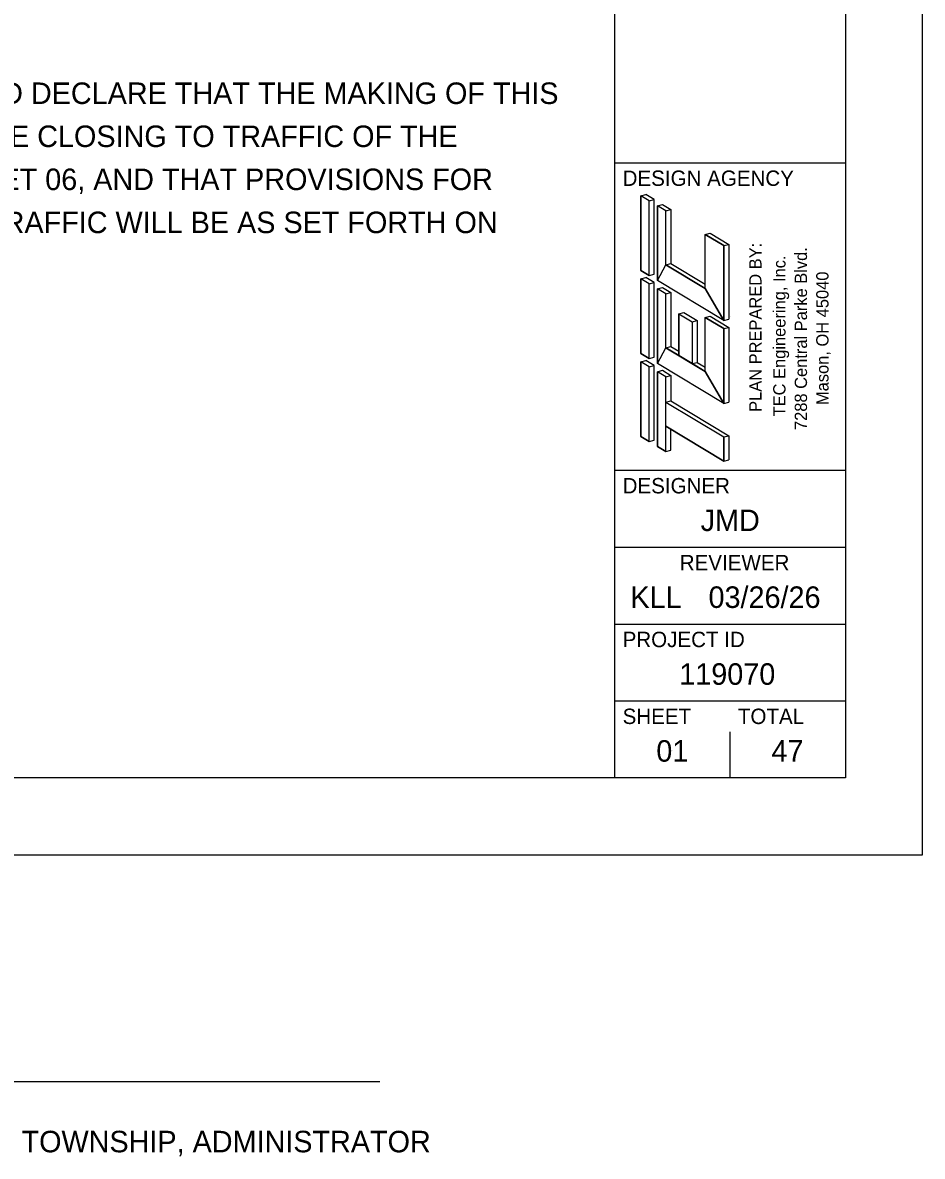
# Model space of a CAD drawing. Extents: x 0 to 34, y -2 to 22.
# Drawn here: x 28.15 to 34, y -1.96 to 5.41 of the extents above; entities that cross this region are included whole.
import ezdxf

# ---------------------------------------------------------------- set-up
doc = ezdxf.new("R2010")
doc.units = 0
for name, color, linetype in [('Default', 7, 'Continuous'), ('SH_Border', 7, 'Continuous'), ('SH_Cut_Line', 7, 'Continuous'), ('SH_Data', 7, 'Continuous'), ('SH_Text', 7, 'Continuous')]:
    doc.layers.add(name, color=color, linetype=linetype)

msp = doc.modelspace()

# ---------------------------------------------------------------- linework, layer by layer
at = {"layer": 'Default'}
msp.add_line((25.7726, -1.4745), (30.4698, -1.4745), dxfattribs=at)
at = {"layer": 'SH_Border'}
for p, q in [((32, 0.5), (32, 21.5)), ((32, 4.5), (33.5, 4.5)), ((32, 2.5), (33.5, 2.5)), ((32, 2), (33.5, 2)), ((32, 1.5), (33.5, 1.5)), ((32, 1), (33.5, 1))]:
    msp.add_line(p, q, dxfattribs=at)
msp.add_lwpolyline([(1.5, 21.5), (33.5, 21.5), (33.5, 0.5), (1.5, 0.5)], close=True, dxfattribs=at)
at = {"layer": 'SH_Cut_Line'}
msp.add_lwpolyline([(0, 0), (34, 0), (34, 22), (0, 22)], close=True, dxfattribs=at)
at = {"layer": 'SH_Data'}
for p, q in [((32.75, 3.5), (32.75, 3.5)), ((32.75, 0.5), (32.75, 0.8)), ((32.375, 0.675), (32.375, 0.675))]:
    msp.add_line(p, q, dxfattribs=at)
at = {"layer": 'SH_Text'}
for p, q in [((32.1688, 4.2855), (32.2012, 4.2936)), ((32.1688, 3.7995), (32.1688, 4.2855)), ((32.2228, 4.2531), (32.1688, 4.2855)), ((32.2552, 4.2612), (32.2012, 4.2936)), ((32.2228, 4.2531), (32.2552, 4.2612)), ((32.2228, 3.7671), (32.2228, 4.2531)), ((32.2552, 3.7752), (32.2552, 4.2612)), ((32.2768, 4.2207), (32.3092, 4.2288)), ((32.3308, 4.1883), (32.2768, 4.2207)), ((32.2768, 3.7347), (32.2768, 4.2207)), ((32.3092, 4.2288), (32.3632, 4.1964)), ((32.3308, 4.1883), (32.3632, 4.1964)), ((32.3308, 3.8373), (32.3308, 4.1883)), ((32.3632, 4.1964), (32.3632, 3.8454)), ((32.5873, 4.0344), (32.6197, 4.0425)), ((32.5873, 3.6834), (32.5873, 4.0344)), ((32.7088, 3.9615), (32.5873, 4.0344)), ((32.6197, 4.0425), (32.7412, 3.9696)), ((32.7088, 3.9615), (32.7412, 3.9696)), ((32.7088, 3.4755), (32.7088, 3.9615)), ((32.7412, 3.9696), (32.7412, 3.4836)), ((32.3308, 3.8373), (32.3632, 3.8454)), ((32.5873, 3.6834), (32.3308, 3.8373)), ((32.3632, 3.8454), (32.5873, 3.7109)), ((32.2228, 3.7671), (32.1688, 3.7995)), ((32.2228, 3.7671), (32.2552, 3.7752)), ((32.1688, 3.7455), (32.2012, 3.7536)), ((32.1688, 3.2595), (32.1688, 3.7455)), ((32.2228, 3.7131), (32.1688, 3.7455)), ((32.2547, 3.7224), (32.2012, 3.7536)), ((32.2228, 3.7131), (32.2547, 3.7224)), ((32.2228, 3.2271), (32.2228, 3.7131)), ((32.2547, 3.2364), (32.2547, 3.7224)), ((32.7088, 3.4755), (32.2768, 3.7347)), ((32.2768, 3.6807), (32.3092, 3.6888)), ((32.3092, 3.6888), (32.3632, 3.6564)), ((32.2768, 3.1947), (32.2768, 3.6807)), ((32.3308, 3.6483), (32.2768, 3.6807)), ((32.3308, 3.6483), (32.3632, 3.6564)), ((32.3308, 3.2973), (32.3308, 3.6483)), ((32.3632, 3.6564), (32.3632, 3.3054)), ((32.4151, 3.5189), (32.4475, 3.527)), ((32.4151, 3.5189), (32.4151, 3.2466)), ((32.4151, 3.5189), (32.5029, 3.4663)), ((32.4475, 3.527), (32.5353, 3.4744)), ((32.5029, 3.4663), (32.5353, 3.4744)), ((32.5029, 3.4663), (32.5029, 3.194)), ((32.5353, 3.4744), (32.5353, 3.2021)), ((32.5873, 3.4944), (32.6197, 3.5025)), ((32.5873, 3.1434), (32.5873, 3.4944)), ((32.7088, 3.4215), (32.5873, 3.4944)), ((32.6197, 3.5025), (32.7412, 3.4296)), ((32.7088, 3.4755), (32.7412, 3.4836)), ((32.7088, 3.4215), (32.7412, 3.4296)), ((32.7088, 2.9355), (32.7088, 3.4215)), ((32.7412, 3.4296), (32.7412, 2.9436)), ((32.2228, 3.2271), (32.1688, 3.2595)), ((32.3308, 3.2973), (32.3632, 3.3054)), ((32.4151, 3.2466), (32.3308, 3.2973)), ((32.3632, 3.3054), (32.4151, 3.2742)), ((32.1688, 3.2055), (32.2007, 3.2148)), ((32.1688, 2.7195), (32.1688, 3.2055)), ((32.2228, 3.1731), (32.1688, 3.2055)), ((32.2552, 3.1812), (32.2007, 3.2148)), ((32.2223, 3.1733), (32.2552, 3.1812)), ((32.2228, 3.2271), (32.2547, 3.2364)), ((32.2228, 2.6871), (32.2228, 3.1731)), ((32.2552, 2.6952), (32.2552, 3.1812)), ((32.7088, 2.9355), (32.2768, 3.1947)), ((32.5029, 3.194), (32.5353, 3.2021)), ((32.5873, 3.1434), (32.5029, 3.194)), ((32.5353, 3.2021), (32.5873, 3.1709)), ((32.2768, 3.1407), (32.3087, 3.1514)), ((32.3308, 3.1083), (32.2768, 3.1407)), ((32.2768, 2.6547), (32.2768, 3.1407)), ((32.3087, 3.1514), (32.3632, 3.1164)), ((32.3308, 3.1083), (32.3632, 3.1164)), ((32.3308, 2.944), (32.3308, 3.1083)), ((32.3632, 3.1164), (32.3632, 2.9521)), ((32.3308, 2.944), (32.3632, 2.9521)), ((32.3632, 2.9521), (32.7412, 2.7253)), ((32.3308, 2.944), (32.7088, 2.7172)), ((32.7088, 2.9355), (32.7412, 2.9436)), ((32.3308, 2.7865), (32.7088, 2.5597)), ((32.3308, 2.6223), (32.3308, 2.7865)), ((32.3632, 2.6304), (32.3632, 2.7671)), ((32.2228, 2.6871), (32.1688, 2.7195)), ((32.2228, 2.6871), (32.2552, 2.6952)), ((32.3308, 2.6223), (32.2768, 2.6547)), ((32.7088, 2.7172), (32.7412, 2.7253)), ((32.7088, 2.5597), (32.7088, 2.7172)), ((32.7412, 2.7253), (32.7412, 2.5678)), ((32.3308, 2.6223), (32.3632, 2.6304)), ((32.7088, 2.5597), (32.7412, 2.5678))]:
    msp.add_line(p, q, dxfattribs=at)
for points in [[(32.1688, 3.7995), (32.2228, 3.7671), (32.2228, 4.2531), (32.1688, 4.2855)], [(32.2768, 3.7347), (32.3308, 3.8373), (32.3308, 4.1883), (32.2768, 4.2207)], [(32.7088, 3.4755), (32.5873, 3.6834), (32.5873, 4.0344), (32.7088, 3.9615)], [(32.2768, 3.7347), (32.3308, 3.8373), (32.5873, 3.6834), (32.7088, 3.4755)], [(32.1688, 3.2595), (32.2228, 3.2271), (32.2228, 3.7131), (32.1688, 3.7455)], [(32.2768, 3.1947), (32.3308, 3.2973), (32.3308, 3.6483), (32.2768, 3.6807)], [(32.4151, 3.2466), (32.4151, 3.5189), (32.5029, 3.4663), (32.5029, 3.194)], [(32.7088, 2.9355), (32.5873, 3.1434), (32.5873, 3.4944), (32.7088, 3.4215)], [(32.2768, 3.1947), (32.3308, 3.2973), (32.5873, 3.1434), (32.7088, 2.9355)], [(32.1688, 2.7195), (32.2228, 2.6871), (32.2228, 3.1731), (32.1688, 3.2055)], [(32.2768, 2.6547), (32.3308, 2.6223), (32.3308, 3.1083), (32.2768, 3.1407)], [(32.3308, 2.7865), (32.3308, 2.944), (32.7088, 2.7172), (32.7088, 2.5597)]]:
    msp.add_lwpolyline(points, close=True, dxfattribs=at)

# ---------------------------------------------------------------- texts
at = {"layer": 'Default'}
for s, p in [('I HEREBY APPROVE THESE PLANS AND DECLARE THAT THE MAKING OF THIS ', (24.5279, 4.8827)), ('IMPROVEMENT WILL NOT REQUIRE THE CLOSING TO TRAFFIC OF THE ', (24.5279, 4.6027)), ('HIGHWAY EXCEPT AS NOTED ON SHEET 06, AND THAT PROVISIONS FOR ', (24.5279, 4.3227)), ('THE MAINTENANCE AND SAFETY OF TRAFFIC WILL BE AS SET FORTH ON ', (24.5279, 4.0427)), ('DELHI TOWNSHIP, ADMINISTRATOR', (27.5359, -1.9358))]:
    msp.add_text(s, height=0.14, dxfattribs=at).set_placement(p)
for s, p in [('PLAN PREPARED BY:', (32.9537, 2.8801)), ('7288 Central Parke Blvd.', (33.2497, 2.7622)), ('TEC Engineering, Inc.', (33.1097, 2.8507)), ('Mason, OH 45040', (33.3897, 2.9246))]:
    msp.add_text(s, height=0.08, rotation=90, dxfattribs=at).set_placement(p)
at = {"layer": 'SH_Data'}
for s, height, p in [('DESIGN AGENCY', 0.1, (32.05, 4.35)), ('DESIGNER', 0.1, (32.05, 2.35)), ('JMD', 0.14, (32.5577, 2.105)), ('REVIEWER', 0.1, (32.4218, 1.85)), ('KLL', 0.14, (32.1009, 1.605)), ('03/26/26', 0.14, (32.6089, 1.605)), ('PROJECT ID', 0.1, (32.05, 1.35)), ('119070', 0.14, (32.4186, 1.105)), ('SHEET', 0.1, (32.05, 0.85)), ('TOTAL', 0.1, (32.8, 0.85)), ('01', 0.14, (32.2692, 0.605)), ('47', 0.14, (33.0183, 0.605))]:
    msp.add_text(s, height=height, dxfattribs=at).set_placement(p)

doc.saveas('drawing.dxf')
